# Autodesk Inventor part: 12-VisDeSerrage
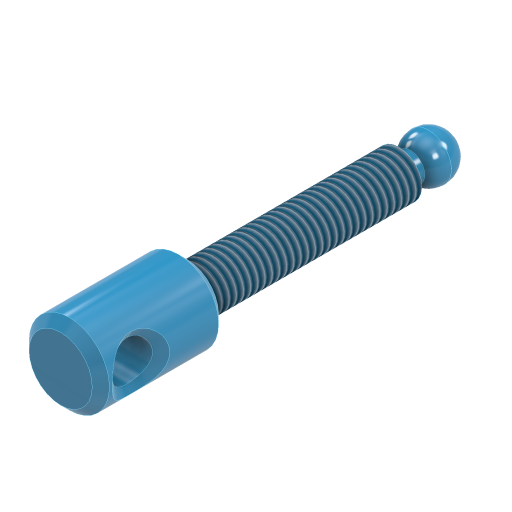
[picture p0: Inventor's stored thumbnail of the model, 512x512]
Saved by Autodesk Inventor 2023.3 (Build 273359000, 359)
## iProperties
Created: 2024-12
Part Number: 12-VisDeSerrage
Material: Générique
Document SubType Name: Modeling
Designer: Thier
Density: 1 g/cm^3
Appearance: Bleu ciel foncé
Author: Thier
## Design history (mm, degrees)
sketch "Esquisse1"
  geometry: L1 (0, 0)-(7, 0); L2 (7, 0)-(7, -22); L3 (7, -22)-(4, -22); L4 (4, -22)-(4, -58.875); L5 (4, -58.875)-(2.5, -58.875); L6 (2.5, -58.875)-(2.5, -60.875); L7 (2.5, -60.875)-(4, -60.875); L8 (0, -68)-(0, 0); L9 (4, -60.875)-(4, -68); L10 (4, -68)-(0, -68); 2 further points
  constraints: 20 end point, 8 perpendicular, 1 coincident, 1 horizontal, 1 midpoint, 1 point on line, 1 vertical
  dimensions: "d0" = 46 vertical distance of L8.start L3.end; "d1" = 8 diameter of L4 L8; "d2" = 14 diameter of L2 L8; "d3" = 22 distance of L1.end L2.end; "d5" = 2 distance of L5.end L6.end; "d6" = 5 diameter of point (2.5, -59.875) L8; "d18" = 7.125 distance of L7.end L9.end
revolve "Révolution1" sketch "Esquisse1" stored, may be unused: angle "d7" = 90 deg
chamfer "Chanfrein1" distance "d8" = 1.5; stored, may be unused: second distance "d9" = 2, angle "d10" = 45 deg
feature "Filetage1" dims "d11" = 33.072, "d12" = 0
sketch "Esquisse2"
  geometry: L1 (-5.5, 0)-(5.5, 0) reference; C1 r 3.5 at (0, -7); 2 further points
  constraints: 1 centre point, 1 midpoint
  dimensions: "d13" = 7 diameter of C1; "d14" = 7 distance from line of C1.centre L1; "d15" = 0 horizontal distance of point (0, 0) C1.centre
extrude "Extrusion1" cut sketch "Esquisse2" stored distance "d16" = 15; taper "d17" = 0 deg
fillet "Congé2" dims "d20" = 4
chamfer "Chanfrein2" distance "d21" = 1.5; stored, may be unused: second distance "d22" = 2, angle "d23" = 45 deg
node "Solide1"
